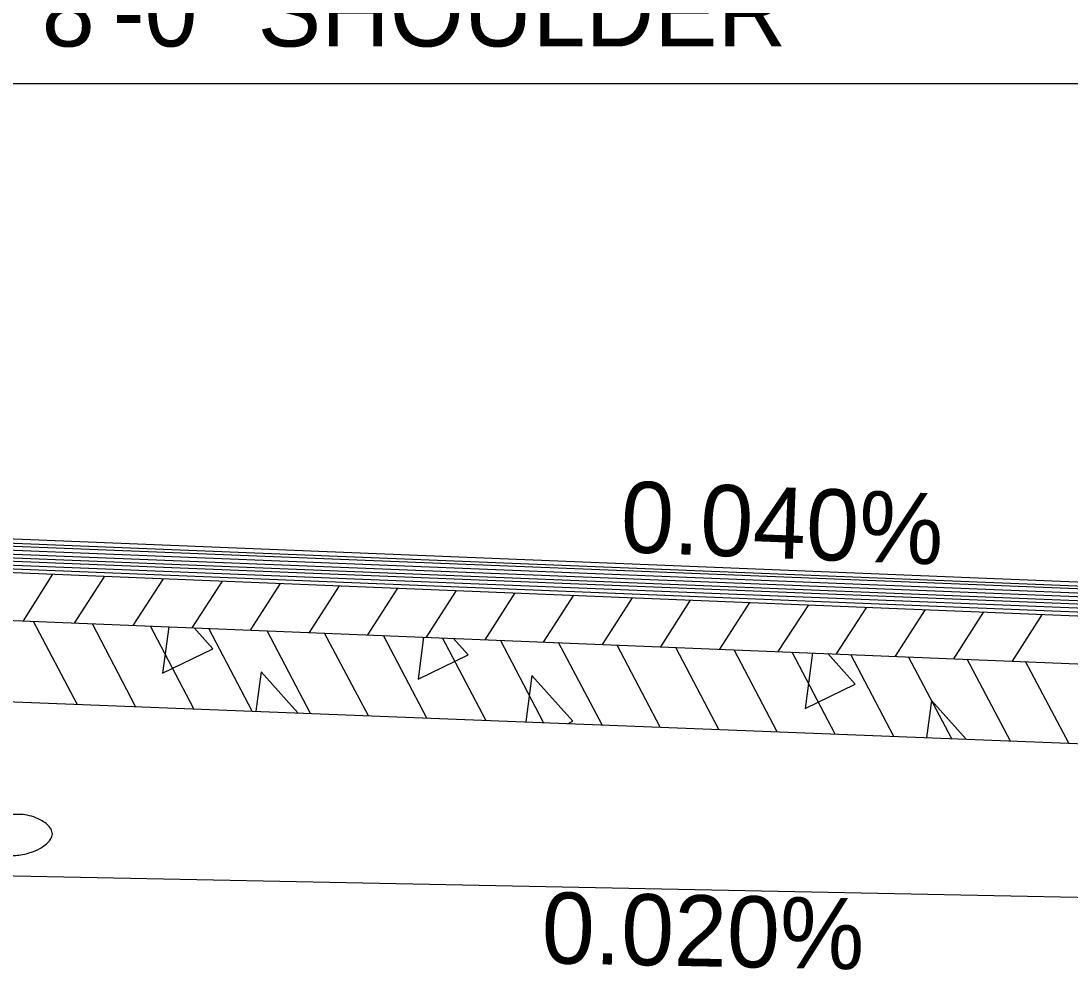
# Model space of a CAD drawing. Extents: x 714919 to 718439, y 1619644 to 1621844.
# Drawn here: x 716609 to 716830.2, y 1620636 to 1620836.2 of the extents above; entities that cross this region are included whole.
import ezdxf

# ---------------------------------------------------------------- set-up
doc = ezdxf.new("R2010")
doc.units = 0
doc.layers.add('Default', color=7, linetype='Continuous')
doc.layers.add('R_Draft', color=7, linetype='Continuous')

msp = doc.modelspace()

# ---------------------------------------------------------------- linework, layer by layer
at = {"layer": 'Default'}
for p, q in [((716454.52, 1620823.01), (717288.2, 1620823.01)), ((716456.83, 1620733.02), (716978.32, 1620712.04)), ((716457.24, 1620732.11), (716978.89, 1620711.13)), ((716457.55, 1620731.42), (716979.25, 1620710.57)), ((716457.93, 1620730.57), (716979.85, 1620709.63)), ((716458.33, 1620729.7), (716980.35, 1620708.84)), ((716458.65, 1620728.98), (716980.93, 1620707.92)), ((716459.01, 1620728.18), (716981.35, 1620707.26)), ((716459.35, 1620727.42), (716981.93, 1620706.35)), ((716459.74, 1620726.55), (716982.43, 1620705.56)), ((716460.07, 1620725.81), (716983.01, 1620704.64)), ((716609.57, 1620709.66), (716615.79, 1620719.51)), ((716620.34, 1620709.22), (716626.72, 1620719.07)), ((716632.71, 1620708.72), (716639.08, 1620718.57)), ((716645.13, 1620708.22), (716651.52, 1620718.06)), ((716657.42, 1620707.72), (716663.77, 1620717.57)), ((716669.85, 1620707.22), (716676.18, 1620717.06)), ((716464.69, 1620715.54), (716989.62, 1620694.24)), ((716682.15, 1620706.72), (716688.49, 1620716.57)), ((716694.53, 1620706.21), (716700.86, 1620716.06)), ((716706.92, 1620705.71), (716713.26, 1620715.56)), ((716719.25, 1620705.21), (716725.64, 1620715.06)), ((716731.65, 1620704.71), (716737.99, 1620714.56)), ((716743.93, 1620704.21), (716750.24, 1620714.07)), ((716756.38, 1620703.7), (716762.73, 1620713.56)), ((716768.73, 1620703.2), (716775.14, 1620713.06)), ((716781.03, 1620702.7), (716787.38, 1620712.56)), ((716793.43, 1620702.2), (716799.76, 1620712.06)), ((716805.72, 1620701.7), (716812.07, 1620711.56)), ((716818.1, 1620701.2), (716824.41, 1620711.06)), ((716620.89, 1620692.1), (716611.71, 1620709.57)), ((716633.21, 1620691.62), (716624.12, 1620709.07)), ((716645.53, 1620691.13), (716636.37, 1620708.57)), ((716657.76, 1620690.65), (716648.64, 1620708.08)), ((716670.1, 1620690.16), (716660.94, 1620707.58)), ((716682.33, 1620689.68), (716673.08, 1620707.08)), ((716694.63, 1620689.19), (716685.49, 1620706.58)), ((716707.03, 1620688.7), (716697.95, 1620706.08)), ((716719.24, 1620688.22), (716710.13, 1620705.58)), ((716731.57, 1620687.73), (716722.38, 1620705.08)), ((716743.85, 1620687.25), (716734.75, 1620704.58)), ((716756.18, 1620686.76), (716747.1, 1620704.08)), ((716768.51, 1620686.28), (716759.41, 1620703.58)), ((716780.74, 1620685.79), (716771.68, 1620703.08)), ((716793.11, 1620685.31), (716784.02, 1620702.58)), ((716805.33, 1620684.82), (716796.18, 1620702.09)), ((716817.69, 1620684.34), (716808.58, 1620701.59)), ((716830, 1620683.85), (716820.88, 1620701.09)), ((716472.6, 1620697.96), (717000.49, 1620677.12)), ((716381.27, 1620660.41), (717288.2, 1620642.27))]:
    msp.add_line(p, q, dxfattribs=at)
msp.add_spline([(716606.82, 1620668.81), (716609.87, 1620668.77), (716613.53, 1620667.48), (716615.38, 1620665.75), (716615.67, 1620664.74), (716614.66, 1620662.87), (716613.59, 1620662.02), (716611.66, 1620661.06), (716608.62, 1620660.29), (716607.13, 1620660.21), (716604.85, 1620660.35), (716602.39, 1620660.79), (716600.48, 1620661.58), (716598.69, 1620662.99), (716598.41, 1620664.26), (716598.95, 1620665.81), (716600.32, 1620666.96), (716601.65, 1620667.82), (716603.62, 1620668.49), (716604.87, 1620668.77), (716606.82, 1620668.81)], degree=3, dxfattribs=at)
at = {"layer": 'R_Draft'}
for p, q in [((716640.21, 1620708.42), (716638.92, 1620698.67)), ((716693.94, 1620706.24), (716692.77, 1620697.37)), ((716775.92, 1620702.91), (716774.37, 1620691.2)), ((716659.67, 1620698.96), (716658.57, 1620690.62)), ((716716.79, 1620698.13), (716715.49, 1620688.37)), ((716801, 1620692.91), (716799.96, 1620685.04))]:
    msp.add_line(p, q, dxfattribs=at)
for points in [[(716638.92, 1620698.67), (716649.49, 1620703.8), (716645.56, 1620708.2)], [(716692.77, 1620697.37), (716703.34, 1620702.5), (716700.22, 1620705.98)], [(716774.37, 1620691.2), (716784.94, 1620696.33), (716779.18, 1620702.78)], [(716667.44, 1620690.27), (716659.67, 1620698.96)], [(716724.42, 1620688.02), (716725.4, 1620688.49), (716716.79, 1620698.13)], [(716808.33, 1620684.7), (716801, 1620692.91)]]:
    msp.add_lwpolyline(points, dxfattribs=at)

# ---------------------------------------------------------------- texts
at = {"layer": 'Default'}
msp.add_text('8\'-0" SHOULDER', height=15, dxfattribs=at).set_placement((716613.44, 1620830.8))
for s, rotation, p in [('0.040%', 357.7077, (716735.3, 1620724.21)), ('0.020%', 358.8543, (716718.73, 1620637.49))]:
    msp.add_text(s, height=15, rotation=rotation, dxfattribs=at).set_placement(p)

doc.saveas('drawing.dxf')
